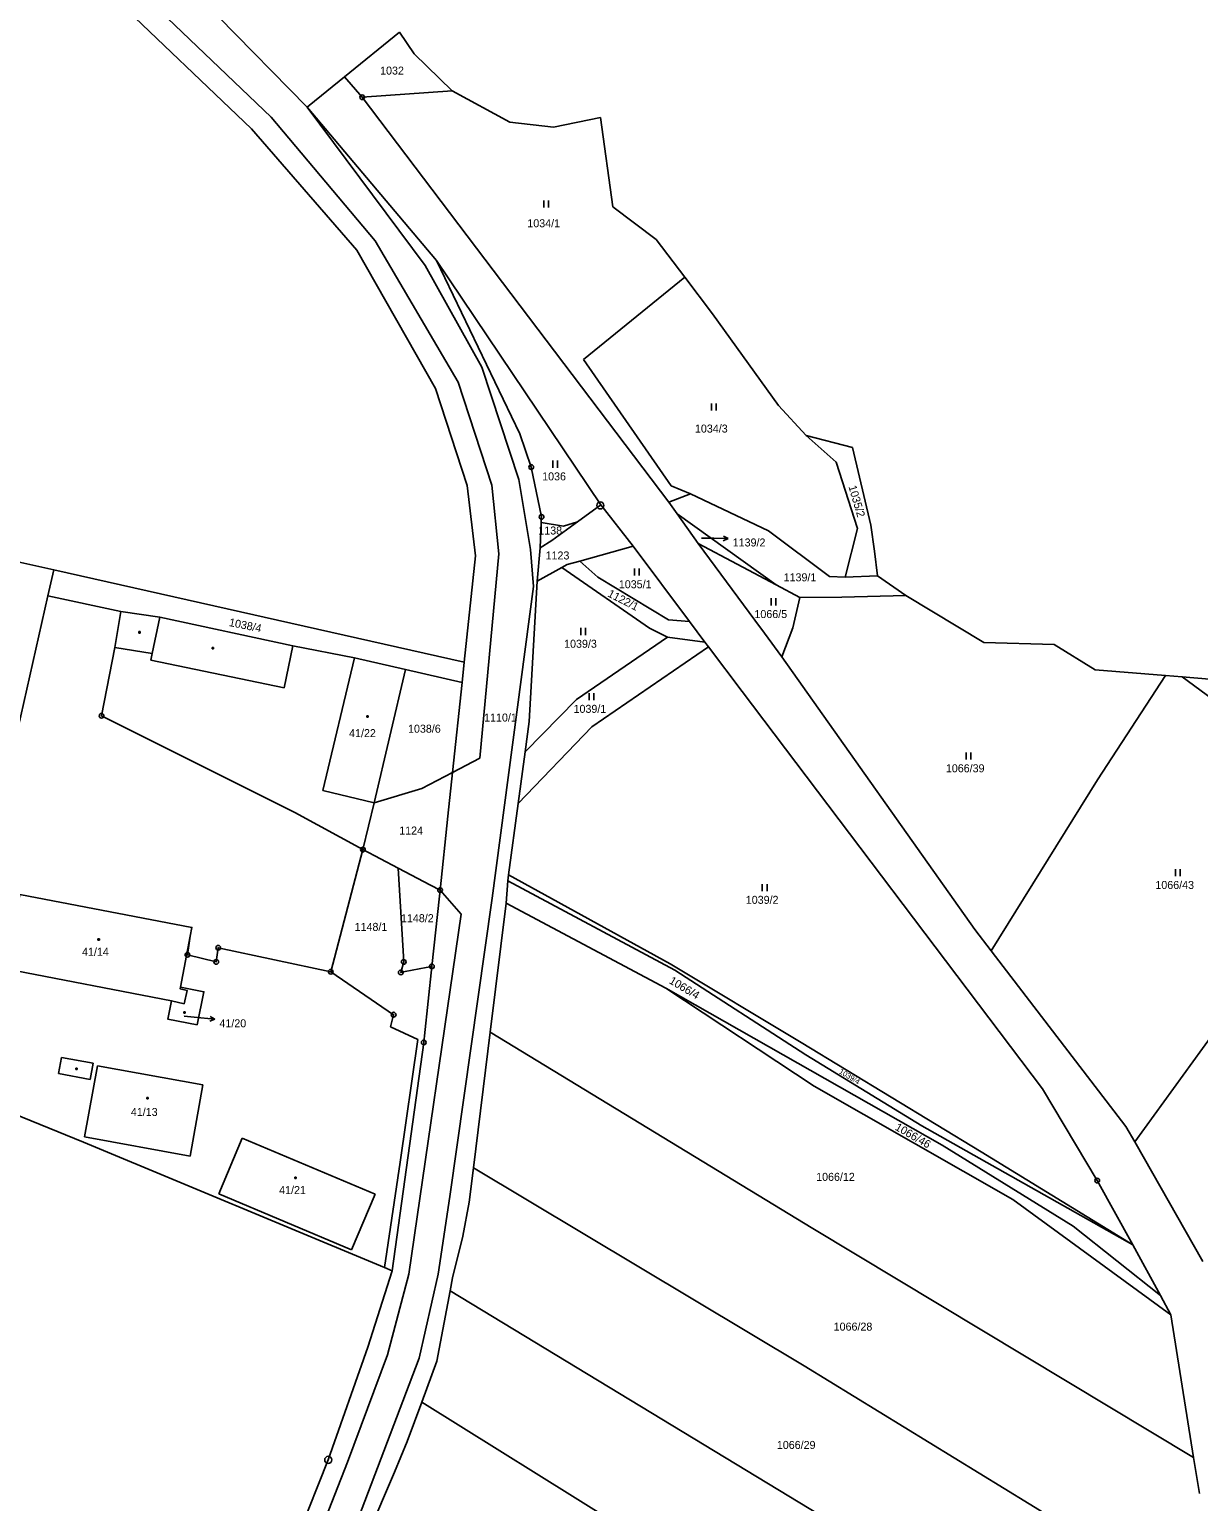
# Model space of a CAD drawing. Extents: x -794142 to -791199, y -1109267 to -1105626.
# Drawn here: x -791697.1 to -791448.6, y -1108658.8 to -1108346 of the extents above; entities that cross this region are included whole.
import ezdxf

# ---------------------------------------------------------------- set-up
doc = ezdxf.new("R2010")
doc.units = 0
for name, color, linetype in [('Komunikace', 7, 'Continuous'), ('Vrstva 1', 7, 'Continuous'), ('Vrstva 14', 7, 'Continuous'), ('Vrstva 15', 7, 'Continuous'), ('Vrstva 16', 7, 'Continuous'), ('Vrstva 2', 7, 'Continuous'), ('Vrstva 23', 7, 'Continuous'), ('Vrstva 25', 7, 'Continuous'), ('Vrstva 28', 7, 'Continuous'), ('Vrstva 4', 7, 'Continuous')]:
    doc.layers.add(name, color=color, linetype=linetype)

msp = doc.modelspace()

# ---------------------------------------------------------------- linework, layer by layer
at = {"layer": 'Komunikace'}
for p, q in [((-791554.21, -1108454.13), (-791551.58, -1108454.16)), ((-791664.2, -1108555.69), (-791660.67, -1108556.05))]:
    msp.add_line(p, q, dxfattribs=at)
at = {"layer": 'Vrstva 1'}
for p, q in [((-791649.91, -1108367.13), (-791683.23, -1108335.35)), ((-791626.34, -1108360.44), (-791630.1, -1108356.1)), ((-791626.34, -1108360.44), (-791607.24, -1108359.08)), ((-791638.05, -1108362.55), (-791610.52, -1108395.12)), ((-791561.17, -1108446.48), (-791626.34, -1108360.44)), ((-791627.46, -1108392.97), (-791649.91, -1108367.13)), ((-791610.76, -1108422.36), (-791627.46, -1108392.97)), ((-791610.52, -1108395.12), (-791575.64, -1108447.07)), ((-791592.85, -1108431.99), (-791610.52, -1108395.12)), ((-791579.32, -1108416.18), (-791557.77, -1108398.69)), ((-791560.65, -1108443.01), (-791579.32, -1108416.18)), ((-791604.02, -1108442.93), (-791610.76, -1108422.36)), ((-791590.42, -1108439.02), (-791592.85, -1108431.99)), ((-791531.97, -1108432.32), (-791525.6, -1108438)), ((-791588.22, -1108449.61), (-791590.42, -1108439.02)), ((-791525.6, -1108438), (-791521.08, -1108452.08)), ((-791602.24, -1108457.89), (-791604.02, -1108442.93)), ((-791556.57, -1108444.7), (-791560.65, -1108443.01)), ((-791556.57, -1108444.7), (-791561.17, -1108446.48)), ((-791559.39, -1108448.99), (-791561.17, -1108446.48)), ((-791556.57, -1108444.7), (-791540, -1108452.61)), ((-791588.27, -1108450.83), (-791588.22, -1108449.61)), ((-791580.58, -1108450.66), (-791575.64, -1108447.07)), ((-791568.76, -1108455.85), (-791575.64, -1108447.07)), ((-791554.94, -1108455.26), (-791559.39, -1108448.99)), ((-791559.39, -1108448.99), (-791538.36, -1108464.08)), ((-791588.5, -1108456.22), (-791588.27, -1108450.83)), ((-791588.27, -1108450.83), (-791583.56, -1108451.56)), ((-791586.06, -1108454.64), (-791580.58, -1108450.66)), ((-791583.56, -1108451.56), (-791580.58, -1108450.66)), ((-791526.99, -1108462.3), (-791540, -1108452.61)), ((-791521.08, -1108452.08), (-791523.67, -1108462.44)), ((-791589.15, -1108463.24), (-791588.5, -1108456.22)), ((-791588.5, -1108456.22), (-791586.06, -1108454.64)), ((-791568.76, -1108455.85), (-791580.08, -1108459)), ((-791568.76, -1108455.85), (-791556.75, -1108471.85)), ((-791554.94, -1108455.26), (-791538.36, -1108464.08)), ((-791554.94, -1108455.26), (-791542.87, -1108471.56)), ((-791706.63, -1108457.59), (-791691.93, -1108460.85)), ((-791604.68, -1108480.5), (-791602.24, -1108457.89)), ((-791580.08, -1108459), (-791582.74, -1108459.74)), ((-791580.08, -1108459), (-791576.24, -1108462.41)), ((-791691.93, -1108460.85), (-791693.19, -1108466.42)), ((-791691.93, -1108460.85), (-791604.68, -1108480.5)), ((-791589.15, -1108463.24), (-791583.94, -1108460.39)), ((-791583.94, -1108460.39), (-791582.74, -1108459.74)), ((-791583.94, -1108460.39), (-791565.25, -1108473.27)), ((-791576.24, -1108462.41), (-791561.23, -1108471.52)), ((-791523.67, -1108462.44), (-791526.99, -1108462.3)), ((-791516.77, -1108462.11), (-791523.67, -1108462.44)), ((-791590.86, -1108493.12), (-791589.15, -1108463.24)), ((-791538.36, -1108464.08), (-791533.31, -1108466.76)), ((-791693.19, -1108466.42), (-791677.68, -1108469.74)), ((-791533.31, -1108466.76), (-791534.83, -1108473.16)), ((-791533.31, -1108466.76), (-791524.4, -1108466.7)), ((-791524.4, -1108466.7), (-791510.76, -1108466.33)), ((-791677.68, -1108469.74), (-791678.91, -1108477.34)), ((-791669.38, -1108470.94), (-791677.68, -1108469.74)), ((-791641.11, -1108477.04), (-791669.38, -1108470.94)), ((-791561.23, -1108471.52), (-791556.75, -1108471.85)), ((-791556.75, -1108471.85), (-791553.48, -1108476.2)), ((-791542.87, -1108471.56), (-791540.82, -1108474.33)), ((-791580.81, -1108488.39), (-791561.47, -1108475.16)), ((-791565.25, -1108473.27), (-791561.47, -1108475.16)), ((-791561.47, -1108475.16), (-791553.48, -1108476.2)), ((-791540.82, -1108474.33), (-791537.11, -1108479.35)), ((-791534.83, -1108473.16), (-791537.11, -1108479.35)), ((-791678.91, -1108477.34), (-791681.76, -1108491.87)), ((-791641.11, -1108477.04), (-791627.96, -1108479.57)), ((-791577.52, -1108494.25), (-791552.73, -1108477.19)), ((-791552.73, -1108477.19), (-791553.48, -1108476.2)), ((-791545.56, -1108486.75), (-791552.73, -1108477.19)), ((-791617.16, -1108482.04), (-791627.96, -1108479.57)), ((-791605.13, -1108484.79), (-791604.68, -1108480.5)), ((-791537.11, -1108479.35), (-791496.12, -1108537.26)), ((-791623.83, -1108510.35), (-791617.16, -1108482.04)), ((-791617.16, -1108482.04), (-791605.13, -1108484.79)), ((-791470.06, -1108505.46), (-791455.6, -1108483.34)), ((-791427.3, -1108501.83), (-791452.02, -1108483.63)), ((-791605.13, -1108484.79), (-791607.16, -1108503.94)), ((-791545.56, -1108486.75), (-791481.76, -1108571.13)), ((-791591.72, -1108499.51), (-791580.81, -1108488.39)), ((-791681.76, -1108491.87), (-791640.64, -1108512.45)), ((-791591.72, -1108499.51), (-791590.86, -1108493.12)), ((-791593.19, -1108510.5), (-791577.52, -1108494.25)), ((-791593.19, -1108510.5), (-791591.72, -1108499.51)), ((-791613.65, -1108507.32), (-791607.16, -1108503.94)), ((-791607.16, -1108503.94), (-791608.14, -1108513.2)), ((-791492.64, -1108541.8), (-791470.06, -1108505.46)), ((-791623.83, -1108510.35), (-791613.65, -1108507.32)), ((-791640.64, -1108512.45), (-791626.19, -1108520.31)), ((-791626.19, -1108520.31), (-791623.83, -1108510.35)), ((-791595.23, -1108525.7), (-791593.19, -1108510.5)), ((-791411.23, -1108512.26), (-791462.13, -1108582.4)), ((-791608.14, -1108513.2), (-791609.79, -1108528.91)), ((-791633.02, -1108546.26), (-791626.19, -1108520.31)), ((-791618.69, -1108524.24), (-791626.19, -1108520.31)), ((-791618.69, -1108524.24), (-791617.52, -1108544.17)), ((-791611.81, -1108527.85), (-791618.69, -1108524.24)), ((-791609.79, -1108528.91), (-791611.81, -1108527.85)), ((-791595.73, -1108531.71), (-791595.4, -1108526.95)), ((-791595.23, -1108525.7), (-791595.4, -1108526.95)), ((-791595.4, -1108526.95), (-791559.87, -1108545.92)), ((-791595.23, -1108525.7), (-791560.85, -1108544.56)), ((-791611.52, -1108545.12), (-791609.93, -1108530.21)), ((-791609.93, -1108530.21), (-791609.79, -1108528.91)), ((-791599.14, -1108559.13), (-791595.73, -1108531.71)), ((-791595.73, -1108531.71), (-791561.79, -1108549.78)), ((-791492.64, -1108541.8), (-791496.12, -1108537.26)), ((-791662.89, -1108538.71), (-791664.95, -1108549.54)), ((-791662.89, -1108538.71), (-791663.49, -1108542.65)), ((-791657.38, -1108544.16), (-791663.49, -1108542.65)), ((-791656.96, -1108541.16), (-791657.38, -1108544.16)), ((-791633.02, -1108546.26), (-791656.96, -1108541.16)), ((-791464.01, -1108579.11), (-791492.64, -1108541.8)), ((-791666.86, -1108552.44), (-791702.12, -1108545.66)), ((-791633.02, -1108546.26), (-791619.66, -1108555.38)), ((-791617.52, -1108544.17), (-791618.15, -1108546.41)), ((-791618.15, -1108546.41), (-791617.19, -1108546.21)), ((-791617.19, -1108546.21), (-791612.73, -1108545.35)), ((-791613.07, -1108559.91), (-791611.52, -1108545.12)), ((-791612.73, -1108545.35), (-791611.52, -1108545.12)), ((-791560.85, -1108544.56), (-791533.04, -1108561.3)), ((-791559.87, -1108545.92), (-791532.01, -1108563.9)), ((-791561.79, -1108549.78), (-791530.3, -1108570.58)), ((-791503.09, -1108583.12), (-791561.79, -1108549.78)), ((-791619.66, -1108555.38), (-791620.36, -1108557.96)), ((-791620.36, -1108557.96), (-791614.54, -1108560.68)), ((-791602.71, -1108587.89), (-791599.14, -1108559.13)), ((-791530.55, -1108600.79), (-791599.14, -1108559.13)), ((-791619.98, -1108609.8), (-791613.25, -1108561.28)), ((-791618.3, -1108586.73), (-791614.54, -1108560.68)), ((-791613.25, -1108561.28), (-791613.07, -1108559.91)), ((-791533.04, -1108561.3), (-791494.74, -1108584.53)), ((-791532.01, -1108563.9), (-791507.37, -1108578.98)), ((-791530.3, -1108570.58), (-791488.07, -1108594.65)), ((-791481.76, -1108571.13), (-791470.1, -1108590.62)), ((-791685.58, -1108582.47), (-791707.85, -1108573.38)), ((-791507.37, -1108578.98), (-791462.56, -1108604.3)), ((-791462.13, -1108582.4), (-791464.01, -1108579.11)), ((-791621.6, -1108609.12), (-791685.58, -1108582.47)), ((-791656.8, -1108593.45), (-791651.87, -1108581.62)), ((-791651.87, -1108581.62), (-791623.62, -1108593.5)), ((-791475.24, -1108600.31), (-791503.09, -1108583.12)), ((-791494.74, -1108584.53), (-791462.56, -1108604.3)), ((-791447.63, -1108607.79), (-791462.13, -1108582.4)), ((-791618.3, -1108586.73), (-791619.53, -1108595.27)), ((-791603.62, -1108595.23), (-791602.71, -1108587.89)), ((-791602.71, -1108587.89), (-791532.37, -1108630.01)), ((-791470.1, -1108590.62), (-791462.56, -1108604.3)), ((-791628.6, -1108605.33), (-791656.8, -1108593.45)), ((-791623.62, -1108593.5), (-791628.6, -1108605.33)), ((-791619.53, -1108595.27), (-791621.6, -1108609.12)), ((-791604.93, -1108602.43), (-791603.62, -1108595.23)), ((-791454.44, -1108619.15), (-791488.07, -1108594.65)), ((-791607.12, -1108611.26), (-791604.93, -1108602.43)), ((-791449.61, -1108649.48), (-791530.55, -1108600.79)), ((-791456.68, -1108615.06), (-791475.24, -1108600.31)), ((-791462.56, -1108604.3), (-791456.68, -1108615.06)), ((-791621.6, -1108609.12), (-791619.98, -1108609.8)), ((-791625.12, -1108626.05), (-791619.98, -1108609.8)), ((-791607.65, -1108614.07), (-791607.12, -1108611.26)), ((-791610.46, -1108629), (-791607.65, -1108614.07)), ((-791607.65, -1108614.07), (-791526.62, -1108663.13)), ((-791456.68, -1108615.06), (-791454.44, -1108619.15)), ((-791454.44, -1108619.15), (-791449.61, -1108649.48)), ((-791633.57, -1108649.97), (-791625.12, -1108626.05)), ((-791610.46, -1108629), (-791613.7, -1108637.7)), ((-791532.37, -1108630.01), (-791446.95, -1108682.34)), ((-791613.7, -1108637.7), (-791616.8, -1108646.04)), ((-791613.7, -1108637.7), (-791572.76, -1108663.24)), ((-791616.8, -1108646.04), (-791619.47, -1108652.6)), ((-791679, -1108764.32), (-791633.57, -1108649.97)), ((-791449.61, -1108649.48), (-791448.39, -1108657.12)), ((-791619.47, -1108652.6), (-791625.93, -1108667.65))]:
    msp.add_line(p, q, dxfattribs=at)
for points in [[(-791699.48, -1108531.91), (-791699.09, -1108529.87), (-791662.54, -1108536.84), (-791662.89, -1108538.71)], [(-791664.95, -1108549.54), (-791660.01, -1108550.5), (-791661.44, -1108557.53), (-791667.63, -1108556.35), (-791666.86, -1108552.44)], [(-791664.95, -1108549.54), (-791665.03, -1108549.9), (-791663.57, -1108550.24), (-791664.22, -1108553.05), (-791666.86, -1108552.44)]]:
    msp.add_lwpolyline(points, dxfattribs=at)
at = {"layer": 'Vrstva 16'}
for p, q in [((-791551.58, -1108454.16), (-791548.58, -1108454.197)), ((-791548.58, -1108454.197), (-791549.586, -1108454.684)), ((-791548.58, -1108454.197), (-791549.573, -1108453.684)), ((-791660.67, -1108556.05), (-791657.685, -1108556.357)), ((-791657.685, -1108556.357), (-791658.731, -1108556.752)), ((-791657.685, -1108556.357), (-791658.629, -1108555.757))]:
    msp.add_line(p, q, dxfattribs=at)
at = {"layer": 'Vrstva 2'}
for p, q in [((-791645.69, -1108364.66), (-791694.69, -1108317.85)), ((-791612.99, -1108396.22), (-791638.05, -1108362.55)), ((-791623.62, -1108390.99), (-791645.69, -1108364.66)), ((-791605.97, -1108420.99), (-791623.62, -1108390.99)), ((-791600.89, -1108417.81), (-791612.99, -1108396.22)), ((-791593.04, -1108441.68), (-791600.89, -1108417.81)), ((-791598.77, -1108442.9), (-791605.97, -1108420.99)), ((-791597.3, -1108457.46), (-791598.77, -1108442.9)), ((-791590.59, -1108456.57), (-791593.04, -1108441.68)), ((-791601.36, -1108500.9), (-791597.3, -1108457.46)), ((-791589.94, -1108464.42), (-791590.59, -1108456.57)), ((-791598.74, -1108530.66), (-791589.94, -1108464.42)), ((-791693.19, -1108466.42), (-791704.49, -1108516.47)), ((-791669.38, -1108470.94), (-791670.97, -1108478.63)), ((-791678.91, -1108477.34), (-791670.97, -1108478.63)), ((-791642.94, -1108485.91), (-791641.11, -1108477.04)), ((-791670.97, -1108478.63), (-791671.27, -1108480.06)), ((-791671.27, -1108480.06), (-791642.94, -1108485.91)), ((-791627.96, -1108479.57), (-791634.68, -1108507.78)), ((-791607.16, -1108503.94), (-791601.36, -1108500.9)), ((-791634.68, -1108507.78), (-791623.83, -1108510.35)), ((-791605.28, -1108534.03), (-791609.79, -1108528.91)), ((-791607.73, -1108593.99), (-791598.74, -1108530.66)), ((-791616.4, -1108610.51), (-791605.28, -1108534.03)), ((-791690.24, -1108564.46), (-791690.87, -1108567.9)), ((-791683.51, -1108565.7), (-791690.24, -1108564.46)), ((-791684.14, -1108569.14), (-791683.51, -1108565.7)), ((-791690.87, -1108567.9), (-791684.14, -1108569.14)), ((-791682.62, -1108566.25), (-791685.35, -1108581.32)), ((-791660.19, -1108570.32), (-791682.62, -1108566.25)), ((-791662.93, -1108585.42), (-791660.19, -1108570.32)), ((-791685.35, -1108581.32), (-791662.93, -1108585.42)), ((-791610.19, -1108610.51), (-791607.73, -1108593.99)), ((-791620.97, -1108627.68), (-791616.4, -1108610.51)), ((-791614.27, -1108628.33), (-791610.19, -1108610.51)), ((-791629.48, -1108650.48), (-791620.97, -1108627.68)), ((-791628.49, -1108665.85), (-791614.27, -1108628.33)), ((-791629.48, -1108650.48), (-791674.27, -1108765.12))]:
    msp.add_line(p, q, dxfattribs=at)
at = {"layer": 'Vrstva 23'}
for p, q in [((-791587.76, -1108383.87), (-791587.76, -1108382.37)), ((-791586.76, -1108382.37), (-791586.76, -1108383.87)), ((-791552.09, -1108426.99), (-791552.09, -1108425.49)), ((-791551.09, -1108425.49), (-791551.09, -1108426.99)), ((-791585.85, -1108439.16), (-791585.85, -1108437.66)), ((-791584.85, -1108437.66), (-791584.85, -1108439.16)), ((-791568.49, -1108462.08), (-791568.49, -1108460.58)), ((-791567.49, -1108460.58), (-791567.49, -1108462.08)), ((-791539.42, -1108468.41), (-791539.42, -1108466.91)), ((-791538.42, -1108466.91), (-791538.42, -1108468.41)), ((-791579.89, -1108474.72), (-791579.89, -1108473.22)), ((-791578.89, -1108473.22), (-791578.89, -1108474.72)), ((-791578.13, -1108488.55), (-791578.13, -1108487.05)), ((-791577.13, -1108487.05), (-791577.13, -1108488.55)), ((-791497.98, -1108501.18), (-791497.98, -1108499.68)), ((-791496.98, -1108499.68), (-791496.98, -1108501.18)), ((-791453.47, -1108525.97), (-791453.47, -1108524.47)), ((-791452.47, -1108524.47), (-791452.47, -1108525.97)), ((-791541.29, -1108529.13), (-791541.29, -1108527.63)), ((-791540.29, -1108527.63), (-791540.29, -1108529.13))]:
    msp.add_line(p, q, dxfattribs=at)
at = {"layer": 'Vrstva 25'}
for p, q in [((-791673.82, -1108473.99), (-791673.52, -1108473.99)), ((-791673.82, -1108474.29), (-791673.82, -1108473.99)), ((-791673.52, -1108474.29), (-791673.82, -1108474.29)), ((-791673.52, -1108473.99), (-791673.52, -1108474.29)), ((-791658.23, -1108477.38), (-791657.93, -1108477.38)), ((-791658.23, -1108477.68), (-791658.23, -1108477.38)), ((-791657.93, -1108477.68), (-791658.23, -1108477.68)), ((-791657.93, -1108477.38), (-791657.93, -1108477.68)), ((-791625.39, -1108491.9), (-791625.09, -1108491.9)), ((-791625.39, -1108492.2), (-791625.39, -1108491.9)), ((-791625.09, -1108492.2), (-791625.39, -1108492.2)), ((-791625.09, -1108491.9), (-791625.09, -1108492.2)), ((-791682.52, -1108539.27), (-791682.22, -1108539.27)), ((-791682.52, -1108539.57), (-791682.52, -1108539.27)), ((-791682.22, -1108539.57), (-791682.52, -1108539.57)), ((-791682.22, -1108539.27), (-791682.22, -1108539.57)), ((-791664.25, -1108554.75), (-791663.95, -1108554.75)), ((-791664.25, -1108555.05), (-791664.25, -1108554.75)), ((-791663.95, -1108555.05), (-791664.25, -1108555.05)), ((-791663.95, -1108554.75), (-791663.95, -1108555.05)), ((-791687.22, -1108566.75), (-791686.92, -1108566.75)), ((-791687.22, -1108567.05), (-791687.22, -1108566.75)), ((-791686.92, -1108567.05), (-791687.22, -1108567.05)), ((-791686.92, -1108566.75), (-791686.92, -1108567.05)), ((-791672.12, -1108572.96), (-791671.82, -1108572.96)), ((-791672.12, -1108573.26), (-791672.12, -1108572.96)), ((-791671.82, -1108573.26), (-791672.12, -1108573.26)), ((-791671.82, -1108572.96), (-791671.82, -1108573.26)), ((-791640.68, -1108589.9), (-791640.38, -1108589.9)), ((-791640.68, -1108590.2), (-791640.68, -1108589.9)), ((-791640.38, -1108590.2), (-791640.68, -1108590.2)), ((-791640.38, -1108589.9), (-791640.38, -1108590.2))]:
    msp.add_line(p, q, dxfattribs=at)
at = {"layer": 'Vrstva 28'}
for centre, radius in [((-791626.34, -1108360.44), 0.5), ((-791626.34, -1108360.44), 0.01), ((-791590.42, -1108439.02), 0.5), ((-791590.42, -1108439.02), 0.01), ((-791575.72, -1108447.18), 0.75), ((-791588.22, -1108449.61), 0.5), ((-791588.22, -1108449.61), 0.01), ((-791575.72, -1108447.18), 0.01), ((-791681.76, -1108491.87), 0.5), ((-791681.76, -1108491.87), 0.01), ((-791626.19, -1108520.31), 0.5), ((-791626.19, -1108520.31), 0.01), ((-791609.79, -1108528.91), 0.5), ((-791609.79, -1108528.91), 0.01), ((-791656.96, -1108541.16), 0.5), ((-791663.49, -1108542.65), 0.5), ((-791663.49, -1108542.65), 0.01), ((-791657.38, -1108544.16), 0.5), ((-791656.96, -1108541.16), 0.01), ((-791617.52, -1108544.17), 0.5), ((-791657.38, -1108544.16), 0.01), ((-791633.02, -1108546.26), 0.5), ((-791633.02, -1108546.26), 0.01), ((-791618.15, -1108546.41), 0.5), ((-791618.15, -1108546.41), 0.01), ((-791617.52, -1108544.17), 0.01), ((-791611.52, -1108545.12), 0.5), ((-791611.52, -1108545.12), 0.01), ((-791619.66, -1108555.38), 0.5), ((-791619.66, -1108555.38), 0.01), ((-791613.25, -1108561.28), 0.5), ((-791613.25, -1108561.28), 0.01), ((-791470.1, -1108590.62), 0.5), ((-791470.1, -1108590.62), 0.01), ((-791633.57, -1108649.97), 0.75), ((-791633.57, -1108649.97), 0.01)]:
    msp.add_circle(centre, radius, dxfattribs=at)
at = {"layer": 'Vrstva 4'}
for p, q in [((-791656.97, -1108343.28), (-791638.05, -1108362.55)), ((-791630.1, -1108356.1), (-791618.42, -1108346.63)), ((-791618.42, -1108346.63), (-791615.27, -1108351.23)), ((-791615.27, -1108351.23), (-791607.24, -1108359.08)), ((-791637.61, -1108362.19), (-791630.1, -1108356.1)), ((-791607.24, -1108359.08), (-791594.93, -1108365.75)), ((-791638.05, -1108362.55), (-791637.61, -1108362.19)), ((-791585.65, -1108366.8), (-791575.69, -1108364.75)), ((-791575.69, -1108364.75), (-791573.05, -1108383.77)), ((-791594.93, -1108365.75), (-791585.65, -1108366.8)), ((-791573.05, -1108383.77), (-791563.84, -1108390.65)), ((-791563.84, -1108390.65), (-791557.77, -1108398.69)), ((-791557.77, -1108398.69), (-791551.88, -1108406.48)), ((-791551.88, -1108406.48), (-791537.82, -1108425.95)), ((-791537.82, -1108425.95), (-791531.97, -1108432.32)), ((-791531.97, -1108432.32), (-791522.12, -1108434.86)), ((-791522.12, -1108434.86), (-791518.2, -1108451.37)), ((-791518.2, -1108451.37), (-791517.46, -1108456.9)), ((-791517.46, -1108456.9), (-791516.77, -1108462.11)), ((-791516.77, -1108462.11), (-791510.76, -1108466.33)), ((-791510.76, -1108466.33), (-791494.17, -1108476.32)), ((-791494.17, -1108476.32), (-791479.27, -1108476.71)), ((-791479.27, -1108476.71), (-791470.54, -1108482.12)), ((-791455.6, -1108483.34), (-791470.54, -1108482.12)), ((-791452.02, -1108483.63), (-791455.6, -1108483.34)), ((-791446.22, -1108484.1), (-791452.02, -1108483.63))]:
    msp.add_line(p, q, dxfattribs=at)

# ---------------------------------------------------------------- texts
at = {"layer": 'Vrstva 14'}
for s, height, p in [('1032', 1.7, (-791622.539, -1108355.64)), ('1034/1', 1.7, (-791591.241, -1108388.08)), ('1034/3', 1.7, (-791555.608, -1108431.7)), ('1036', 1.7, (-791588.089, -1108441.86)), ('1138', 1.7, (-791588.903, -1108453.36)), ('1139/2', 0.1, (-791554.432, -1108454.13)), ('1123', 1.7, (-791587.363, -1108458.66)), ('1139/1', 1.7, (-791536.76, -1108463.31)), ('1035/1', 1.7, (-791571.792, -1108464.78)), ('1066/5', 1.7, (-791542.969, -1108471.11)), ('1039/3', 1.7, (-791583.422, -1108477.42)), ('1039/1', 1.7, (-791581.416, -1108491.25)), ('1038/6', 1.7, (-791616.602, -1108495.47)), ('1110/1', 1.7, (-791600.432, -1108493.1)), ('1066/39', 1.7, (-791502.272, -1108503.88)), ('1124', 1.7, (-791618.479, -1108517.11)), ('1066/43', 1.7, (-791457.738, -1108528.67)), ('1039/2', 1.7, (-791544.802, -1108531.83)), ('1148/2', 1.7, (-791618.102, -1108535.73)), ('1148/1', 1.7, (-791627.955, -1108537.58)), ('1066/12', 1.7, (-791529.845, -1108590.69)), ('1066/28', 1.7, (-791526.122, -1108622.51)), ('1066/29', 1.7, (-791538.202, -1108647.65))]:
    msp.add_text(s, height=height, dxfattribs=at).set_placement(p)
for s, height, rotation, p in [('1035/2', 1.7, 286.33752, (-791522.991, -1108443.178)), ('1122/1', 1.7, 332.94159, (-791574.325, -1108466.453)), ('1038/4', 1.7, 348.58926, (-791654.756, -1108472.786)), ('1066/4', 1.7, 329.09085, (-791561.249, -1108548.61)), ('1039/4', 1.14, 328.92624, (-791525.092, -1108567.762)), ('1066/46', 1.7, 330.01272, (-791513.23, -1108579.746))]:
    msp.add_text(s, height=height, rotation=rotation, dxfattribs=at).set_placement(p)
at = {"layer": 'Vrstva 15'}
for s, height, p in [('41/22', 1.7, (-791629.129, -1108496.41)), ('41/14', 1.7, (-791685.898, -1108542.87)), ('41/20', 0.1, (-791664.389, -1108555.69)), ('41/13', 1.7, (-791675.522, -1108576.9)), ('41/21', 1.7, (-791644.002, -1108593.49))]:
    msp.add_text(s, height=height, dxfattribs=at).set_placement(p)
at = {"layer": 'Vrstva 16'}
for s, p in [('1139/2', (-791547.58, -1108455.9)), ('41/20', (-791656.69, -1108558.06))]:
    msp.add_text(s, height=1.7, dxfattribs=at).set_placement(p)

doc.saveas('drawing.dxf')
